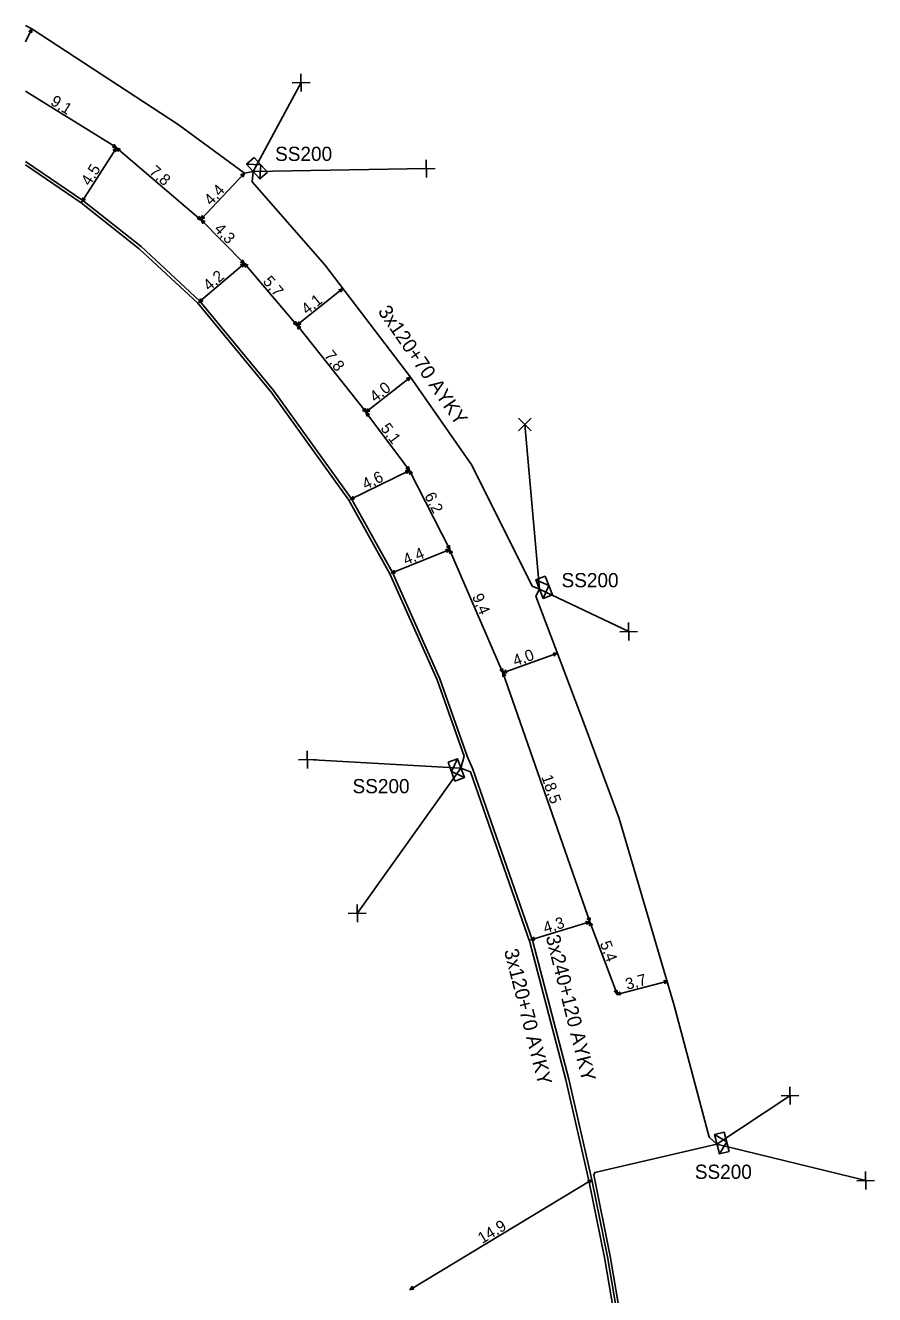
# Model space of a CAD drawing. Extents: x -761250 to -761165, y -1152671 to -1152488.
# Drawn here: x -761250 to -761190.6, y -1152577.3 to -1152488.4 of the extents above; entities that cross this region are included whole.
import ezdxf

# ---------------------------------------------------------------- set-up
doc = ezdxf.new("R2010")
doc.units = 0
for name, color, linetype in [('Vrstva 31', 7, 'Continuous'), ('Vrstva 33', 7, 'Continuous'), ('Vrstva 34', 7, 'Continuous'), ('Vrstva 40', 7, 'Continuous'), ('Vrstva 5', 7, 'Continuous'), ('Vrstva 59', 7, 'Continuous'), ('Vrstva 6', 7, 'Continuous')]:
    doc.layers.add(name, color=color, linetype=linetype)

msp = doc.modelspace()

# ---------------------------------------------------------------- linework, layer by layer
at = {"layer": 'Vrstva 31'}
for points in [[(-761233.059, -1152498.704), (-761233.579, -1152499.172), (-761234.516, -1152498.132), (-761233.996, -1152497.663)], [(-761233.059, -1152498.704), (-761233.996, -1152497.663)], [(-761233.528, -1152498.183), (-761234.516, -1152498.132)], [(-761233.528, -1152498.183), (-761233.579, -1152499.172)], [(-761213.104, -1152528.295), (-761213.758, -1152528.546), (-761214.259, -1152527.239), (-761213.606, -1152526.988)], [(-761213.355, -1152527.642), (-761214.259, -1152527.239)], [(-761213.104, -1152528.295), (-761213.606, -1152526.988)], [(-761213.355, -1152527.642), (-761213.758, -1152528.546)], [(-761220.409, -1152540.009), (-761219.751, -1152539.77), (-761219.272, -1152541.085), (-761219.93, -1152541.325)], [(-761220.409, -1152540.009), (-761219.93, -1152541.325)], [(-761220.169, -1152540.667), (-761219.751, -1152539.77)], [(-761220.169, -1152540.667), (-761219.272, -1152541.085)], [(-761200.74, -1152567.263), (-761201.42, -1152567.432), (-761201.758, -1152566.074), (-761201.079, -1152565.904)], [(-761200.91, -1152566.583), (-761201.758, -1152566.074)], [(-761200.74, -1152567.263), (-761201.079, -1152565.904)], [(-761200.91, -1152566.583), (-761201.42, -1152567.432)]]:
    msp.add_lwpolyline(points, dxfattribs=at)
at = {"layer": 'Vrstva 34'}
for points in [[(-761231.325, -1152492.441), (-761230.075, -1152492.419)], [(-761230.689, -1152493.055), (-761230.711, -1152491.805)], [(-761221.919, -1152499.075), (-761221.941, -1152497.825)], [(-761222.555, -1152498.461), (-761221.305, -1152498.439)], [(-761215.472, -1152515.928), (-761214.588, -1152516.812)], [(-761215.472, -1152516.812), (-761214.588, -1152515.928)], [(-761207.759, -1152531.485), (-761207.781, -1152530.235)], [(-761208.395, -1152530.871), (-761207.145, -1152530.849)], [(-761230.249, -1152540.455), (-761230.271, -1152539.205)], [(-761230.885, -1152539.841), (-761229.635, -1152539.819)], [(-761226.759, -1152551.215), (-761226.781, -1152549.965)], [(-761227.395, -1152550.601), (-761226.145, -1152550.579)], [(-761196.469, -1152563.985), (-761196.491, -1152562.735)], [(-761197.105, -1152563.371), (-761195.855, -1152563.349)], [(-761191.169, -1152569.925), (-761191.191, -1152568.675)], [(-761191.805, -1152569.311), (-761190.555, -1152569.289)]]:
    msp.add_lwpolyline(points, dxfattribs=at)
at = {"layer": 'Vrstva 40'}
for points in [[(-761249.54, -1152488.65), (-761250, -1152489.56)], [(-761243.62, -1152496.98), (-761250, -1152493.02)], [(-761246.04, -1152500.77), (-761243.63, -1152496.99)], [(-761237.69, -1152502.05), (-761243.63, -1152497)], [(-761234.67, -1152498.77), (-761237.71, -1152502)], [(-761234.68, -1152505.1), (-761237.69, -1152502.04)], [(-761237.85, -1152507.81), (-761234.67, -1152505.09)], [(-761234.67, -1152505.09), (-761230.99, -1152509.42)], [(-761227.78, -1152506.85), (-761230.99, -1152509.42)], [(-761230.98, -1152509.41), (-761226.15, -1152515.51)], [(-761223.05, -1152513.05), (-761226.16, -1152515.51)], [(-761223.12, -1152519.58), (-761226.16, -1152515.51)], [(-761227.26, -1152521.61), (-761223.12, -1152519.58)], [(-761220.3, -1152525.11), (-761223.12, -1152519.58)], [(-761224.39, -1152526.77), (-761220.3, -1152525.11)], [(-761216.58, -1152533.74), (-761220.31, -1152525.11)], [(-761212.76, -1152532.38), (-761216.58, -1152533.74)], [(-761216.57, -1152533.73), (-761210.49, -1152551.18)], [(-761214.63, -1152552.44), (-761210.49, -1152551.18)], [(-761210.5, -1152551.18), (-761208.58, -1152556.26)], [(-761205.03, -1152555.33), (-761208.61, -1152556.27)], [(-761223.09, -1152576.94), (-761210.35, -1152569.25)]]:
    msp.add_lwpolyline(points, dxfattribs=at)
for points in [[(-761249.539, -1152488.648), (-761249.554, -1152488.917), (-761249.742, -1152488.825)], [(-761243.618, -1152496.982), (-761243.885, -1152496.943), (-761243.777, -1152496.764)], [(-761243.628, -1152496.988), (-761243.671, -1152497.254), (-761243.848, -1152497.143)], [(-761243.632, -1152496.998), (-761243.374, -1152497.078), (-761243.509, -1152497.238)], [(-761234.668, -1152498.768), (-761234.761, -1152499.021), (-761234.914, -1152498.879)], [(-761246.042, -1152500.772), (-761245.998, -1152500.506), (-761245.821, -1152500.617)], [(-761237.688, -1152502.052), (-761237.946, -1152501.972), (-761237.812, -1152501.812)], [(-761237.711, -1152502.002), (-761237.618, -1152501.749), (-761237.465, -1152501.892)], [(-761237.692, -1152502.038), (-761237.442, -1152502.14), (-761237.59, -1152502.288)], [(-761234.678, -1152505.102), (-761234.928, -1152505), (-761234.78, -1152504.852)], [(-761234.668, -1152505.088), (-761234.787, -1152505.33), (-761234.924, -1152505.173)], [(-761234.672, -1152505.088), (-761234.43, -1152505.207), (-761234.588, -1152505.344)], [(-761237.852, -1152507.812), (-761237.733, -1152507.57), (-761237.596, -1152507.727)], [(-761227.777, -1152506.849), (-761227.905, -1152507.086), (-761228.036, -1152506.924)], [(-761230.989, -1152509.422), (-761231.231, -1152509.303), (-761231.073, -1152509.166)], [(-761230.992, -1152509.421), (-761230.865, -1152509.184), (-761230.733, -1152509.346)], [(-761230.982, -1152509.408), (-761230.744, -1152509.536), (-761230.907, -1152509.667)], [(-761223.048, -1152513.049), (-761223.175, -1152513.286), (-761223.307, -1152513.124)], [(-761226.149, -1152515.512), (-761226.387, -1152515.385), (-761226.224, -1152515.253)], [(-761226.162, -1152515.511), (-761226.035, -1152515.274), (-761225.903, -1152515.436)], [(-761226.162, -1152515.508), (-761225.928, -1152515.644), (-761226.095, -1152515.77)], [(-761223.118, -1152519.579), (-761223.292, -1152519.785), (-761223.387, -1152519.599)], [(-761223.119, -1152519.583), (-761223.352, -1152519.447), (-761223.185, -1152519.321)], [(-761223.121, -1152519.577), (-761222.915, -1152519.752), (-761223.101, -1152519.846)], [(-761227.262, -1152521.611), (-761227.088, -1152521.405), (-761226.993, -1152521.591)], [(-761220.297, -1152525.109), (-761220.485, -1152525.303), (-761220.567, -1152525.11)], [(-761220.299, -1152525.112), (-761220.505, -1152524.938), (-761220.318, -1152524.843)], [(-761220.31, -1152525.108), (-761220.114, -1152525.292), (-761220.305, -1152525.377)], [(-761224.392, -1152526.771), (-761224.204, -1152526.577), (-761224.123, -1152526.77)], [(-761212.758, -1152532.38), (-761212.955, -1152532.563), (-761213.027, -1152532.367)], [(-761216.579, -1152533.743), (-761216.776, -1152533.558), (-761216.585, -1152533.473)], [(-761216.57, -1152533.728), (-761216.387, -1152533.925), (-761216.584, -1152533.997)], [(-761216.582, -1152533.74), (-761216.384, -1152533.557), (-761216.313, -1152533.753)], [(-761210.487, -1152551.179), (-761210.694, -1152551.352), (-761210.755, -1152551.152)], [(-761210.489, -1152551.182), (-761210.672, -1152550.985), (-761210.476, -1152550.913)], [(-761210.501, -1152551.177), (-761210.314, -1152551.372), (-761210.51, -1152551.447)], [(-761214.632, -1152552.441), (-761214.425, -1152552.268), (-761214.364, -1152552.468)], [(-761205.028, -1152555.33), (-761205.241, -1152555.495), (-761205.295, -1152555.293)], [(-761208.58, -1152556.262), (-761208.766, -1152556.068), (-761208.571, -1152555.993)], [(-761208.612, -1152556.271), (-761208.399, -1152556.105), (-761208.345, -1152556.307)], [(-761210.348, -1152569.249), (-761210.503, -1152569.469), (-761210.614, -1152569.292)], [(-761223.093, -1152576.942), (-761222.937, -1152576.721), (-761222.827, -1152576.898)]]:
    msp.add_lwpolyline(points, close=True, dxfattribs=at)
at = {"layer": 'Vrstva 5'}
for points in [[(-761207.45, -1152584.06), (-761209.06, -1152574.6), (-761210.22, -1152568.9), (-761210.15, -1152568.73), (-761201.59, -1152566.75), (-761202.14, -1152566.26), (-761204.58, -1152557.04), (-761208.43, -1152543.95), (-761210.8, -1152537.58), (-761214.27, -1152528.39), (-761214.01, -1152527.89), (-761214.52, -1152527.68), (-761218.76, -1152519.21), (-761223.05, -1152513.05), (-761229.04, -1152505.18), (-761234.13, -1152499.37), (-761234.05, -1152498.65), (-761234.67, -1152498.77), (-761239.31, -1152495.36), (-761249.54, -1152488.65), (-761250, -1152488.42)], [(-761207.65, -1152584.09), (-761209.26, -1152574.64), (-761210.35, -1152569.25), (-761211.96, -1152562.2), (-761214.49, -1152552.55), (-761218.69, -1152540.5), (-761219.07, -1152539.58), (-761221, -1152534.17), (-761224.3, -1152526.73), (-761227.18, -1152521.56), (-761232.61, -1152514), (-761237.78, -1152507.74), (-761241.9, -1152503.9), (-761245.98, -1152500.69), (-761250, -1152497.95)], [(-761207.85, -1152584.12), (-761209.46, -1152574.68), (-761210.55, -1152569.29), (-761212.16, -1152562.25), (-761214.69, -1152552.61), (-761218.85, -1152540.68), (-761219.51, -1152540.43), (-761219.29, -1152539.58), (-761221.18, -1152534.25), (-761224.48, -1152526.82), (-761227.35, -1152521.66), (-761232.77, -1152514.12), (-761237.92, -1152507.88), (-761242.03, -1152504.06), (-761246.1, -1152500.85), (-761250, -1152498.19)]]:
    msp.add_lwpolyline(points, dxfattribs=at)
at = {"layer": 'Vrstva 59'}
for points in [[(-761234.05, -1152498.65), (-761230.7, -1152492.43)], [(-761234.05, -1152498.65), (-761221.93, -1152498.45)], [(-761214.01, -1152527.89), (-761215.03, -1152516.37)], [(-761214.01, -1152527.89), (-761207.77, -1152530.86)], [(-761219.51, -1152540.43), (-761230.26, -1152539.83)], [(-761219.51, -1152540.43), (-761226.77, -1152550.59)], [(-761201.59, -1152566.75), (-761196.48, -1152563.36)], [(-761201.59, -1152566.75), (-761191.18, -1152569.3)]]:
    msp.add_lwpolyline(points, dxfattribs=at)

# ---------------------------------------------------------------- texts
at = {"layer": 'Vrstva 33'}
for p in [(-761232.52, -1152497.91), (-761212.47, -1152527.76), (-761227.1, -1152542.18), (-761203.14, -1152569.18)]:
    msp.add_text('SS200', height=0.9943, dxfattribs=at).set_placement(p)
at = {"layer": 'Vrstva 40'}
for s, rotation, p in [('9,1', 328.19899, (-761248.31, -1152493.93)), ('4,5', 57.42293, (-761245.5, -1152499.71)), ('7,8', 319.69656, (-761241.39, -1152498.75)), ('4,4', 46.75198, (-761237, -1152501.08)), ('4,3', 314.55602, (-761236.84, -1152502.73)), ('4,2', 40.48826, (-761237.14, -1152507.05)), ('5,7', 310.34418, (-761233.42, -1152506.37)), ('4,1', 38.6781, (-761230.29, -1152508.71)), ('7,8', 308.38702, (-761229.13, -1152511.56)), ('4,0', 38.3703, (-761225.51, -1152514.85)), ('5,1', 306.80576, (-761225.18, -1152516.63)), ('4,6', 26.09396, (-761226.19, -1152520.95)), ('6,2', 296.98627, (-761222.09, -1152521.35)), ('4,4', 22.11091, (-761223.37, -1152526.23)), ('9,4', 293.37834, (-761218.75, -1152528.4)), ('4,0', 19.50634, (-761215.71, -1152533.3)), ('18,5', 289.19396, (-761213.89, -1152541.04)), ('4,3', 16.84549, (-761213.61, -1152552)), ('5,4', 290.79882, (-761209.8, -1152552.69)), ('3,7', 14.75989, (-761207.88, -1152555.95)), ('14,9', 31.11229, (-761218.03, -1152573.75))]:
    msp.add_text(s, height=0.7954, rotation=rotation, dxfattribs=at).set_placement(p)
at = {"layer": 'Vrstva 6'}
for s, height, rotation, p in [('3x120+70 AYKY', 0.99428, 304.57683, (-761225.36, -1152508.45)), ('3x240+120 AYKY', 0.99429, 284.13113, (-761213.58, -1152552.22)), ('3x120+70 AYKY', 0.99429, 284.30906, (-761216.5, -1152553.2))]:
    msp.add_text(s, height=height, rotation=rotation, dxfattribs=at).set_placement(p)

doc.saveas('drawing.dxf')
